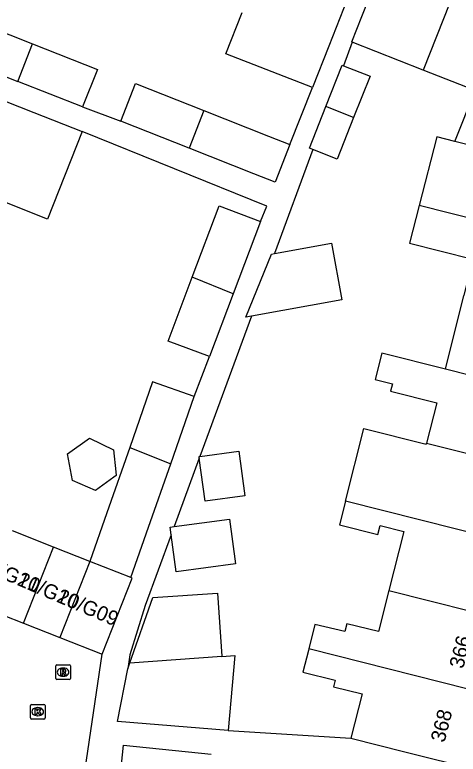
# Model space of a CAD drawing. Extents: x 161253 to 161848, y 384872 to 385383.
# Drawn here: x 161619.1 to 161649.5, y 385046.9 to 385097.6 of the extents above; entities that cross this region are included whole.
import ezdxf

# ---------------------------------------------------------------- set-up
doc = ezdxf.new("R2010")
doc.units = 0
for name, color, linetype in [('IMGEO_Kolk', 7, 'Continuous'), ('IMGEO_Pand', 7, 'Continuous'), ('IMGEO_Pand_nummerreeks', 7, 'Continuous'), ('IMGEO_Rijbaan_lokaal_open', 7, 'Continuous'), ('IMGEO_Rioolput', 7, 'Continuous'), ('IMGEO_Voetpad_open', 7, 'Continuous')]:
    doc.layers.add(name, color=color, linetype=linetype)

msp = doc.modelspace()

# ---------------------------------------------------------------- linework, layer by layer
at = {"layer": 'IMGEO_Kolk'}
for p, q in [((161620.184, 385049.368), (161620.184, 385050.22)), ((161620.259, 385050.294), (161621.111, 385050.294)), ((161621.185, 385050.22), (161621.185, 385049.368)), ((161620.672, 385050.074), (161620.697, 385050.074)), ((161621.111, 385049.294), (161620.259, 385049.294)), ((161620.695, 385049.514), (161620.67, 385049.514))]:
    msp.add_line(p, q, dxfattribs=at)
for points in [[(161620.184, 385049.368), (161620.184, 385050.22)], [(161620.259, 385050.294), (161621.111, 385050.294)], [(161621.185, 385050.22), (161621.185, 385049.368)], [(161620.505, 385049.994), (161620.628, 385049.994), (161620.628, 385049.843), (161620.758, 385049.994), (161620.922, 385049.994), (161620.776, 385049.843), (161620.929, 385049.594), (161620.777, 385049.594), (161620.692, 385049.758), (161620.628, 385049.691), (161620.628, 385049.594), (161620.505, 385049.594), (161620.505, 385049.994)], [(161621.111, 385049.294), (161620.259, 385049.294)]]:
    msp.add_lwpolyline(points, dxfattribs=at)
for centre, start, end in [((161620.261, 385050.218), 91.552, 178.448), ((161620.261, 385050.218), 91.552, 178.448), ((161621.109, 385050.218), 1.552, 88.448), ((161621.109, 385050.218), 1.552, 88.448), ((161620.261, 385049.37), 181.552, 268.448), ((161620.261, 385049.37), 181.552, 268.448), ((161621.109, 385049.37), 271.552, 358.448), ((161621.109, 385049.37), 271.552, 358.448)]:
    msp.add_arc(centre, 0.0765, start, end, dxfattribs=at)
for centre, major_axis, ratio, start_param, end_param in [((161620.671, 385049.794), (-0.387, 0.002), 0.722429, 4.712389, 7.853982), ((161620.696, 385049.794), (-0.39, 0.002), 0.717154, 1.570796, 4.712389)]:
    msp.add_ellipse(centre, major_axis=major_axis, ratio=ratio, start_param=start_param, end_param=end_param, dxfattribs=at)
at = {"layer": 'IMGEO_Pand'}
for points in [[(161643.642, 385103.129), (161640.622, 385095.425), (161639.51, 385092.589)], [(161642.238, 385095.704), (161642.197, 385095.72), (161642.887, 385097.469), (161644.937, 385102.67)], [(161649.844, 385100.733), (161647.102, 385093.79)], [(161614.636, 385094.855), (161615.65, 385097.431), (161620.326, 385095.589)], [(161639.51, 385092.589), (161633.583, 385094.893), (161634.689, 385097.731)], [(161619.318, 385093.011), (161620.326, 385095.589)], [(161620.326, 385095.589), (161624.77, 385093.838), (161623.756, 385091.263)], [(161647.102, 385093.79), (161642.238, 385095.704)], [(161614.636, 385094.855), (161619.318, 385093.011)], [(161612.677, 385093.93), (161617.33, 385092.097), (161620.425, 385090.878), (161623.722, 385089.58)], [(161640.43, 385091.283), (161641.552, 385094.122), (161641.644, 385094.086)], [(161641.644, 385094.086), (161643.454, 385093.37), (161642.331, 385090.531)], [(161649.268, 385088.892), (161650.646, 385092.395), (161647.102, 385093.79)], [(161623.756, 385091.263), (161619.318, 385093.011)], [(161626.377, 385090.292), (161627.391, 385092.868), (161632.074, 385091.023)], [(161632.074, 385091.023), (161631.069, 385088.444)], [(161632.074, 385091.023), (161636.5, 385089.247), (161637.964, 385088.681)], [(161639.537, 385088.353), (161639.307, 385088.444), (161640.43, 385091.283)], [(161642.331, 385090.531), (161640.43, 385091.283)], [(161631.069, 385088.444), (161626.377, 385090.292)], [(161642.331, 385090.531), (161641.209, 385087.692), (161639.537, 385088.353)], [(161623.722, 385089.58), (161621.352, 385083.563), (161618.055, 385084.861)], [(161649.268, 385088.892), (161648.033, 385089.205), (161646.818, 385084.494)], [(161651.254, 385088.388), (161649.268, 385088.892)], [(161637.964, 385088.681), (161636.964, 385086.097), (161635.485, 385086.669), (161631.069, 385088.444)], [(161631.269, 385079.579), (161633.123, 385084.488), (161635.956, 385083.418)], [(161646.818, 385084.494), (161646.154, 385081.921), (161650.498, 385080.82), (161649.879, 385078.335)], [(161659.654, 385081.261), (161646.818, 385084.494)], [(161635.956, 385083.418), (161634.082, 385078.455)], [(161636.912, 385081.209), (161640.815, 385081.913), (161641.516, 385078.03), (161635.334, 385076.913)], [(161635.334, 385076.913), (161634.937, 385076.841), (161636.704, 385081.171), (161636.912, 385081.209)], [(161632.453, 385074.14), (161629.619, 385075.21), (161631.269, 385079.579)], [(161634.082, 385078.455), (161631.269, 385079.579)], [(161634.082, 385078.455), (161632.453, 385074.14)], [(161648.616, 385073.271), (161649.879, 385078.335)], [(161648.616, 385073.271), (161644.261, 385074.371), (161643.809, 385072.581), (161644.991, 385072.282), (161644.863, 385071.776), (161648.02, 385070.979), (161647.322, 385068.217)], [(161657.09, 385071.131), (161648.616, 385073.271)], [(161631.405, 385071.41), (161628.56, 385072.404), (161626.99, 385067.908)], [(161629.797, 385066.802), (161631.405, 385071.41)], [(161641.769, 385064.236), (161643.026, 385069.21), (161647.3, 385068.13), (161647.322, 385068.217)], [(161624.639, 385064.968), (161623.06, 385065.638), (161622.733, 385067.469), (161624.224, 385068.545), (161625.881, 385067.762), (161626.04, 385066.235), (161626.065, 385065.998), (161625.908, 385065.884), (161624.639, 385064.968)], [(161647.322, 385068.217), (161655.811, 385066.071)], [(161626.99, 385067.908), (161625.428, 385063.434), (161624.266, 385060.105)], [(161626.99, 385067.908), (161629.797, 385066.802)], [(161631.801, 385067.298), (161634.458, 385067.655), (161634.869, 385064.595), (161632.151, 385064.23), (161631.756, 385067.174)], [(161631.756, 385067.174), (161631.74, 385067.29), (161631.801, 385067.298)], [(161627.072, 385058.999), (161628.274, 385062.44), (161629.797, 385066.802)], [(161641.769, 385064.236), (161641.358, 385062.608), (161643.986, 385061.944), (161644.144, 385062.57), (161645.767, 385062.16), (161644.741, 385058.102)], [(161654.533, 385061.011), (161641.769, 385064.236)], [(161630.035, 385062.492), (161633.823, 385063.001), (161634.235, 385059.933), (161630.169, 385059.387), (161629.828, 385061.927)], [(161629.828, 385061.927), (161629.757, 385062.455), (161630.035, 385062.492)], [(161621.771, 385061.087), (161618.953, 385062.198)], [(161619.711, 385055.856), (161621.771, 385061.087)], [(161624.266, 385060.105), (161621.771, 385061.087)], [(161624.266, 385060.105), (161622.205, 385054.874)], [(161627.072, 385058.999), (161624.266, 385060.105)], [(161625.106, 385053.731), (161627.167, 385058.962), (161627.072, 385058.999)], [(161627.006, 385053.142), (161628.582, 385057.621), (161632.994, 385057.929), (161633.294, 385053.613)], [(161644.741, 385058.102), (161644.032, 385055.295), (161641.855, 385055.811), (161641.734, 385055.297), (161639.678, 385055.785), (161639.253, 385054.107)], [(161644.741, 385058.102), (161653.254, 385055.951)], [(161616.892, 385056.967), (161619.711, 385055.856)], [(161619.711, 385055.856), (161622.205, 385054.874)], [(161622.205, 385054.874), (161625.106, 385053.731)], [(161639.253, 385054.107), (161639.226, 385054.001), (161638.85, 385052.515), (161641.073, 385051.953), (161640.961, 385051.508), (161642.912, 385051.015), (161642.146, 385047.983)], [(161651.975, 385050.892), (161639.253, 385054.107)], [(161627.006, 385053.142), (161633.294, 385053.613)], [(161633.294, 385053.613), (161633.296, 385053.589), (161634.195, 385053.653), (161633.732, 385048.516)], [(161626.864, 385052.737), (161627.006, 385053.142)], [(161633.732, 385048.516), (161626.146, 385049.118), (161626.864, 385052.737)], [(161642.146, 385047.983), (161645.847, 385047.047), (161650.694, 385045.822)], [(161626.039, 385042.415), (161626.568, 385047.499), (161632.575, 385046.872)]]:
    msp.add_lwpolyline(points, dxfattribs=at)
at = {"layer": 'IMGEO_Rijbaan_lokaal_open'}
msp.add_lwpolyline([(161622.619, 385044.542), (161623.721, 385044.472), (161625.106, 385053.731)], dxfattribs=at)
at = {"layer": 'IMGEO_Rioolput'}
for p, q in [((161621.919, 385052.08), (161621.919, 385052.932)), ((161621.994, 385053.006), (161622.846, 385053.006)), ((161622.407, 385052.786), (161622.432, 385052.786)), ((161622.92, 385052.932), (161622.92, 385052.08)), ((161622.846, 385052.006), (161621.994, 385052.006)), ((161622.43, 385052.226), (161622.405, 385052.226))]:
    msp.add_line(p, q, dxfattribs=at)
for points in [[(161621.919, 385052.08), (161621.919, 385052.932)], [(161621.994, 385053.006), (161622.846, 385053.006)], [(161622.92, 385052.932), (161622.92, 385052.08)], [(161622.508, 385052.704), (161622.256, 385052.706), (161622.256, 385052.306)], [(161622.256, 385052.306), (161622.38, 385052.306), (161622.38, 385052.468), (161622.391, 385052.468)], [(161622.434, 385052.625), (161622.38, 385052.625), (161622.38, 385052.544)], [(161622.38, 385052.544), (161622.432, 385052.544)], [(161622.438, 385052.439), (161622.509, 385052.306), (161622.649, 385052.306), (161622.584, 385052.432)], [(161622.846, 385052.006), (161621.994, 385052.006)]]:
    msp.add_lwpolyline(points, dxfattribs=at)
for centre, radius, start, end in [((161621.996, 385052.93), 0.0765, 91.552, 178.448), ((161621.996, 385052.93), 0.0765, 91.552, 178.448), ((161622.844, 385052.93), 0.0765, 1.552, 88.448), ((161622.844, 385052.93), 0.0765, 1.552, 88.448), ((161622.39, 385052.415), 0.0533, 26.0293, 88.6989), ((161622.416, 385052.733), 0.19, 274.7715, 282.9687), ((161622.44, 385052.529), 0.0964, 77.0061, 93.1865), ((161622.454, 385052.586), 0.0378, 276.6634, 79.6772), ((161622.507, 385052.594), 0.109, 350.3612, 89.416), ((161622.505, 385052.594), 0.112, 277.5842, 350.9817), ((161622.489, 385052.379), 0.108, 29.5134, 73.7905), ((161621.996, 385052.082), 0.0765, 181.552, 268.448), ((161621.996, 385052.082), 0.0765, 181.552, 268.448), ((161622.844, 385052.082), 0.0765, 271.552, 358.448), ((161622.844, 385052.082), 0.0765, 271.552, 358.448)]:
    msp.add_arc(centre, radius, start, end, dxfattribs=at)
for centre, major_axis, ratio, start_param, end_param in [((161622.406, 385052.506), (-0.387, 0.002), 0.722429, 4.712389, 7.853982), ((161622.431, 385052.506), (-0.39, 0.002), 0.717154, 1.570796, 4.712389)]:
    msp.add_ellipse(centre, major_axis=major_axis, ratio=ratio, start_param=start_param, end_param=end_param, dxfattribs=at)
at = {"layer": 'IMGEO_Voetpad_open'}
for points in [[(161642.238, 385095.704), (161641.644, 385094.086)], [(161637.964, 385088.681), (161639.51, 385092.589)], [(161623.756, 385091.263), (161626.377, 385090.292)], [(161635.956, 385083.418), (161636.375, 385084.451), (161623.722, 385089.58)], [(161639.537, 385088.353), (161636.912, 385081.209)], [(161635.334, 385076.913), (161631.801, 385067.298)], [(161631.405, 385071.41), (161632.453, 385074.14)], [(161631.756, 385067.174), (161630.035, 385062.492)], [(161629.828, 385061.927), (161628.048, 385057.083), (161626.986, 385053.694), (161626.864, 385052.737)], [(161633.732, 385048.516), (161642.146, 385047.983)]]:
    msp.add_lwpolyline(points, dxfattribs=at)

# ---------------------------------------------------------------- texts
at = {"layer": 'IMGEO_Pand_nummerreeks'}
for s, rotation, p in [('20/G11', 336.9671, (161616.526, 385059.645)), ('20/G10', 336.9671, (161619.214, 385058.502)), ('20/G09', 336.9671, (161621.911, 385057.356)), ('366', 75.8195, (161649.832, 385052.695)), ('368', 75.8195, (161648.553, 385047.637))]:
    msp.add_text(s, height=1, rotation=rotation, dxfattribs=at).set_placement(p)

doc.saveas('drawing.dxf')
